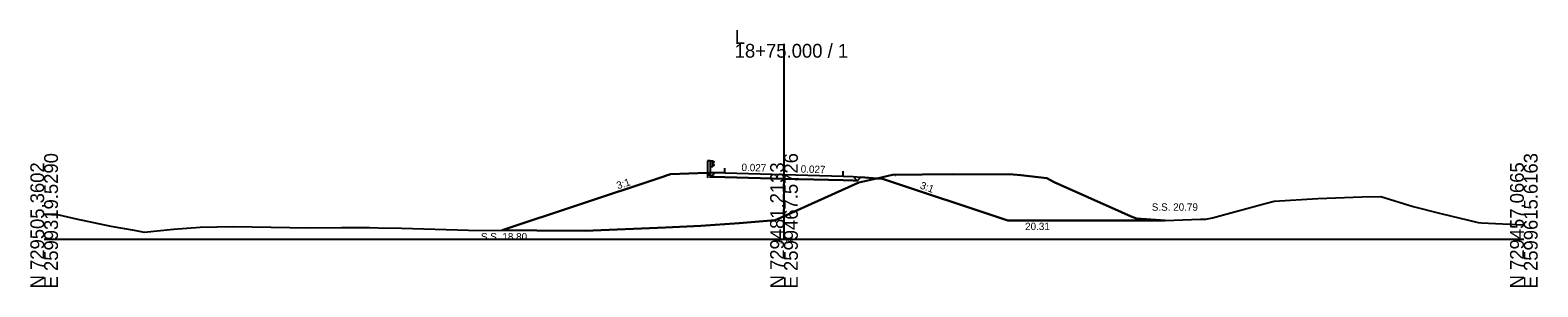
# Model space of a CAD drawing. Extents: x -26 to 3303, y -10 to 9555.
# Drawn here: x 997.2 to 1302.8, y 7490.3 to 7542.5 of the extents above; entities that cross this region are included whole.
import ezdxf

# ---------------------------------------------------------------- set-up
doc = ezdxf.new("R2010")
doc.units = 0
for name, color, linetype in [('Exist Cross Section Cell', 7, 'Continuous'), ('Exist XS Center Line Elevation Label', 7, 'Continuous'), ('Exist XS Ground Line', 7, 'Continuous'), ('Prop XS Ditch Slope Text', 7, 'Continuous'), ('Prop XS Ditch Standard Text', 7, 'Continuous'), ('Prop XS Dump Level', 7, 'Continuous'), ('Prop XS Earthwork Shape', 7, 'Continuous'), ('Prop XS EOT Tick Mark', 7, 'Continuous'), ('Prop XS Finish Grade', 7, 'Continuous'), ('Prop XS Finish Grade Earthwork', 7, 'Continuous'), ('Prop XS Finish Grade Paved Shoulder', 7, 'Continuous'), ('Prop XS Finish Grade Pavement', 7, 'Continuous'), ('Prop XS Pvmt Edge Slope', 7, 'Continuous'), ('Prop XS SE Text', 7, 'Continuous'), ('Prop XS Side Slope Text', 7, 'Continuous'), ('Prop XS SS Elevation Text', 7, 'Continuous'), ('Prop XS Subgrade Earthwork', 7, 'Continuous'), ('Typical Guardrail CELL', 7, 'Continuous')]:
    doc.layers.add(name, color=color, linetype=linetype)

msp = doc.modelspace()

# ---------------------------------------------------------------- linework, layer by layer
at = {"layer": 'Exist Cross Section Cell'}
for p, q in [((1150, 7500), (1150, 7539.66)), ((1000, 7500), (1150, 7500)), ((1150, 7500), (1300, 7500))]:
    msp.add_line(p, q, dxfattribs=at)
at = {"layer": 'Exist XS Ground Line'}
msp.add_lwpolyline([(1000, 7505.1), (1002.99, 7504.91), (1006.46, 7504.13), (1013.5, 7502.67), (1018.26, 7501.83), (1020.25, 7501.42), (1026.19, 7502), (1031.65, 7502.44), (1038.37, 7502.59), (1049.8, 7502.4), (1053.73, 7502.3), (1060.29, 7502.36), (1065.95, 7502.39), (1067.74, 7502.33), (1072.47, 7502.24), (1086, 7501.84), (1099.86, 7501.77), (1109.68, 7501.68), (1125.95, 7502.4), (1133.14, 7502.73), (1140.9, 7503.25), (1148.21, 7503.84), (1150, 7504.65), (1165.14, 7511.54), (1171.97, 7513.06), (1184.08, 7513.22), (1196.43, 7513.16), (1198, 7512.98), (1203.27, 7512.38), (1204.78, 7511.59), (1218.46, 7505.5), (1220.38, 7504.58), (1221.47, 7504.17), (1227.29, 7503.79), (1234.41, 7504.04), (1235.52, 7504.04), (1236.86, 7504.32), (1247.54, 7507.22), (1249.36, 7507.72), (1258.24, 7508.24), (1267.22, 7508.6), (1270.99, 7508.65), (1277.59, 7506.61), (1283.16, 7505.19), (1290.73, 7503.37), (1291.41, 7503.35), (1300, 7502.92)], dxfattribs=at)
at = {"layer": 'Prop XS Dump Level'}
for p, q in [((1138, 7513.44), (1150, 7513.11)), ((1150, 7513.11), (1162, 7512.79))]:
    msp.add_line(p, q, dxfattribs=at)
at = {"layer": 'Prop XS Earthwork Shape'}
for points in [[(1164.86, 7511.88), (1165.59, 7512.61), (1168.79, 7512.35), (1165.14, 7511.54), (1150, 7504.65), (1148.21, 7503.84), (1140.9, 7503.25), (1133.14, 7502.73), (1125.95, 7502.4), (1109.68, 7501.68), (1099.86, 7501.77), (1092.83, 7501.8), (1124.39, 7512.32), (1127, 7513.19), (1134.43, 7513.44), (1135.19, 7512.68), (1136, 7512.66), (1138, 7512.6), (1150, 7512.28), (1162, 7511.95), (1164, 7511.9)], [(1092.83, 7501.8), (1099.86, 7501.77), (1109.68, 7501.68), (1125.95, 7502.4), (1133.14, 7502.73), (1140.9, 7503.25), (1148.21, 7503.84), (1150, 7504.65), (1165.14, 7511.54), (1168.79, 7512.35), (1165.59, 7512.61), (1164.86, 7511.88), (1164, 7511.9), (1162, 7511.95), (1150, 7512.28), (1138, 7512.6), (1136, 7512.66), (1135.19, 7512.68), (1134.43, 7513.44), (1127, 7513.19), (1124.39, 7512.32)], [(1168.79, 7512.35), (1171.97, 7513.06), (1184.08, 7513.22), (1196.43, 7513.16), (1198, 7512.98), (1203.27, 7512.38), (1204.78, 7511.59), (1218.46, 7505.5), (1220.38, 7504.58), (1221.47, 7504.17), (1227.29, 7503.79), (1195.4, 7503.79), (1170, 7512.25)], [(1168.79, 7512.35), (1170, 7512.25), (1195.4, 7503.79), (1227.29, 7503.79), (1221.47, 7504.17), (1220.38, 7504.58), (1218.46, 7505.5), (1204.78, 7511.59), (1203.27, 7512.38), (1198, 7512.98), (1196.43, 7513.16), (1184.08, 7513.22), (1171.97, 7513.06)]]:
    msp.add_lwpolyline(points, close=True, dxfattribs=at)
at = {"layer": 'Prop XS EOT Tick Mark'}
for p, q in [((1138, 7513.44), (1138, 7514.44)), ((1162, 7512.79), (1162, 7513.79))]:
    msp.add_line(p, q, dxfattribs=at)
at = {"layer": 'Prop XS Finish Grade'}
for p, q in [((1136, 7513.49), (1134.43, 7513.44)), ((1164, 7512.73), (1165.59, 7512.61))]:
    msp.add_line(p, q, dxfattribs=at)
at = {"layer": 'Prop XS Finish Grade Earthwork'}
for p, q in [((1124.39, 7512.32), (1092.83, 7501.8)), ((1127, 7513.19), (1124.39, 7512.32)), ((1134.43, 7513.44), (1127, 7513.19)), ((1165.59, 7512.61), (1170, 7512.25)), ((1170, 7512.25), (1195.4, 7503.79)), ((1227.29, 7503.79), (1195.4, 7503.79))]:
    msp.add_line(p, q, dxfattribs=at)
at = {"layer": 'Prop XS Finish Grade Paved Shoulder'}
for p, q in [((1138, 7513.44), (1136, 7513.49)), ((1162, 7512.79), (1164, 7512.73))]:
    msp.add_line(p, q, dxfattribs=at)
at = {"layer": 'Prop XS Finish Grade Pavement'}
for p, q in [((1138, 7513.44), (1150, 7513.11)), ((1150, 7513.11), (1162, 7512.79))]:
    msp.add_line(p, q, dxfattribs=at)
at = {"layer": 'Prop XS Pvmt Edge Slope'}
for p, q in [((1135.19, 7512.68), (1134.43, 7513.44)), ((1136, 7513.49), (1135.19, 7512.68)), ((1164, 7512.73), (1164.86, 7511.88)), ((1164.86, 7511.88), (1165.59, 7512.61))]:
    msp.add_line(p, q, dxfattribs=at)
at = {"layer": 'Prop XS Subgrade Earthwork'}
for p, q in [((1135.19, 7512.68), (1134.43, 7513.44)), ((1136, 7512.66), (1135.19, 7512.68)), ((1138, 7512.6), (1136, 7512.66)), ((1150, 7512.28), (1138, 7512.6)), ((1162, 7511.95), (1150, 7512.28)), ((1162, 7511.95), (1164, 7511.9)), ((1164, 7511.9), (1164.86, 7511.88)), ((1164.86, 7511.88), (1165.59, 7512.61))]:
    msp.add_line(p, q, dxfattribs=at)
at = {"layer": 'Typical Guardrail CELL'}
for p, q in [((1135, 7515.94), (1134.5, 7515.94)), ((1134.5, 7515.94), (1134.5, 7513.46)), ((1135, 7515.94), (1135, 7513.46)), ((1135, 7515.94), (1135.5, 7515.94)), ((1135, 7514.78), (1135.5, 7514.78)), ((1135.5, 7515.94), (1135.5, 7514.78)), ((1135.5, 7515.94), (1135.79, 7515.74)), ((1135.5, 7515.41), (1135.79, 7515.61)), ((1135.5, 7515.36), (1135.5, 7515.41)), ((1135.5, 7515.36), (1135.5, 7515.32)), ((1135.5, 7515.32), (1135.79, 7515.11)), ((1135.5, 7514.78), (1135.79, 7514.99)), ((1135, 7513.46), (1134.5, 7513.46)), ((1134.5, 7513.46), (1134.5, 7512.45)), ((1135, 7513.46), (1135, 7512.45))]:
    msp.add_line(p, q, dxfattribs=at)
for centre, start, end in [((1135.74, 7515.68), 304.9888, 54.997), ((1135.74, 7515.05), 304.9634, 54.9941)]:
    msp.add_arc(centre, 0.0776, start, end, dxfattribs=at)

# ---------------------------------------------------------------- texts
at = {"layer": 'Exist Cross Section Cell'}
for s, p in [('L', (1140, 7539.66)), ('18+75.000 / 1', (1140, 7536.86))]:
    msp.add_text(s, height=2.8, dxfattribs=at).set_placement(p)
for s, p in [('E 2599319.5290', (1002.8, 7490)), ('E 2599467.5726', (1152.8, 7490)), ('E 2599615.6163', (1302.8, 7490)), ('N 729505.3602', (1000, 7490)), ('N 729481.2133', (1150, 7490)), ('N 729457.0665', (1300, 7490))]:
    msp.add_text(s, height=2.8, rotation=90, dxfattribs=at).set_placement(p)
at = {"layer": 'Exist XS Center Line Elevation Label'}
msp.add_text('21.65', height=1, dxfattribs=at).set_placement((1148.39, 7499.15))
at = {"layer": 'Prop XS Ditch Slope Text'}
msp.add_text('3:1', height=1.5, rotation=340.2493, dxfattribs=at).set_placement((1177.46, 7510.32))
at = {"layer": 'Prop XS Ditch Standard Text'}
msp.add_text('20.31', height=1.5, dxfattribs=at).set_placement((1198.88, 7501.85))
at = {"layer": 'Prop XS Dump Level'}
for s, height, p in [('Case1', 0.04, (1130, 7513.25)), ('Case1', 0.04, (1170, 7512.21)), ('Eop', 0.3, (1171.97, 7512.76)), ('Eop', 0.3, (1171.97, 7512.76))]:
    msp.add_text(s, height=height, dxfattribs=at).set_placement(p)
at = {"layer": 'Prop XS SE Text'}
for p in [(1141.37, 7513.85), (1153.37, 7513.52)]:
    msp.add_text('0.027', height=1.5, rotation=358.451, dxfattribs=at).set_placement(p)
at = {"layer": 'Prop XS Side Slope Text'}
msp.add_text('3:1', height=1.5, rotation=18.4349, dxfattribs=at).set_placement((1116.33, 7510.11))
at = {"layer": 'Prop XS SS Elevation Text'}
for s, p in [('S.S. 20.79', (1224.56, 7505.77)), ('S.S. 18.80', (1088.55, 7499.75))]:
    msp.add_text(s, height=1.5, dxfattribs=at).set_placement(p)

doc.saveas('drawing.dxf')
